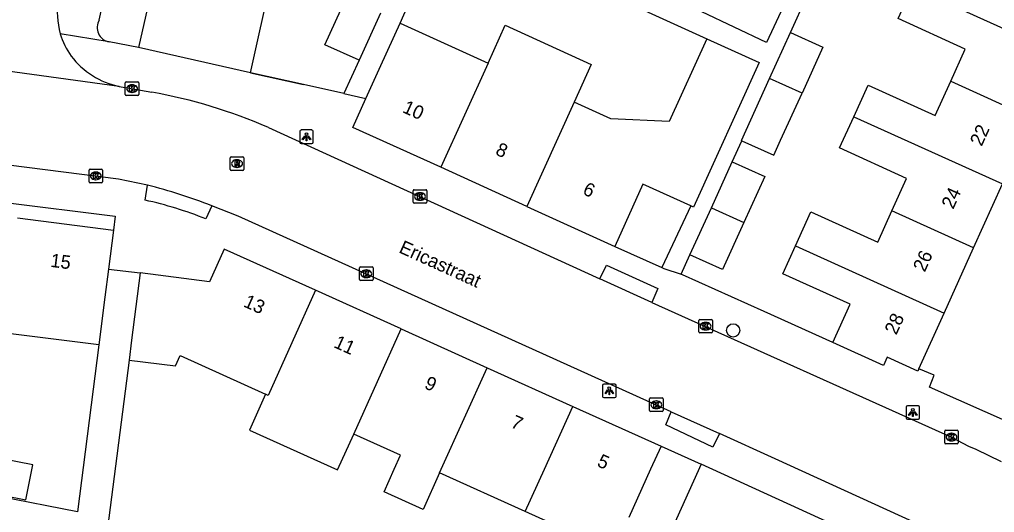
# Model space of a CAD drawing. Extents: x 161845 to 162341, y 381620 to 382158.
# Drawn here: x 162001.2 to 162073, y 381746.8 to 381783.1 of the extents above; entities that cross this region are included whole.
import ezdxf

# ---------------------------------------------------------------- set-up
doc = ezdxf.new("R2010")
doc.units = 0
for name, color, linetype in [('IMGEO_Boom', 7, 'Continuous'), ('IMGEO_Kolk', 7, 'Continuous'), ('IMGEO_Lichtpunt', 7, 'Continuous'), ('IMGEO_Muur', 7, 'Continuous'), ('IMGEO_Openbare_ruimte_label', 7, 'Continuous'), ('IMGEO_Pand', 7, 'Continuous'), ('IMGEO_Pand_nummerreeks', 7, 'Continuous'), ('IMGEO_Rijbaan_lokaal_open', 7, 'Continuous'), ('IMGEO_Rioolput', 7, 'Continuous'), ('IMGEO_Voetpad_open', 7, 'Continuous')]:
    doc.layers.add(name, color=color, linetype=linetype)

msp = doc.modelspace()

# ---------------------------------------------------------------- linework, layer by layer
at = {"layer": 'IMGEO_Boom'}
msp.add_circle((162053.769, 381760.227), 0.489, dxfattribs=at)
at = {"layer": 'IMGEO_Kolk'}
for p, q in [((162009.009, 381777.612), (162009.009, 381778.464)), ((162009.084, 381778.538), (162009.936, 381778.538)), ((162009.497, 381778.318), (162009.522, 381778.318)), ((162010.01, 381778.464), (162010.01, 381777.612)), ((162009.936, 381777.538), (162009.084, 381777.538)), ((162009.52, 381777.758), (162009.495, 381777.758)), ((162006.336, 381771.18), (162006.336, 381772.032)), ((162006.411, 381772.106), (162007.263, 381772.106)), ((162006.824, 381771.886), (162006.849, 381771.886)), ((162007.337, 381772.032), (162007.337, 381771.18)), ((162007.263, 381771.106), (162006.411, 381771.106)), ((162006.847, 381771.326), (162006.822, 381771.326)), ((162030.211, 381769.668), (162030.211, 381770.52)), ((162030.286, 381770.594), (162031.138, 381770.594)), ((162030.699, 381770.374), (162030.724, 381770.374)), ((162031.212, 381770.52), (162031.212, 381769.668)), ((162030.722, 381769.814), (162030.697, 381769.814)), ((162031.138, 381769.594), (162030.286, 381769.594)), ((162026.25, 381763.979), (162026.25, 381764.831)), ((162026.325, 381764.905), (162027.177, 381764.905)), ((162026.738, 381764.685), (162026.763, 381764.685)), ((162027.251, 381764.831), (162027.251, 381763.979)), ((162027.177, 381763.905), (162026.325, 381763.905)), ((162026.761, 381764.125), (162026.736, 381764.125)), ((162051.314, 381761.04), (162052.166, 381761.04)), ((162051.239, 381760.114), (162051.239, 381760.966)), ((162051.727, 381760.82), (162051.752, 381760.82)), ((162052.24, 381760.966), (162052.24, 381760.114)), ((162052.166, 381760.04), (162051.314, 381760.04)), ((162051.75, 381760.26), (162051.725, 381760.26)), ((162047.69, 381755.25), (162048.542, 381755.25)), ((162047.615, 381754.324), (162047.615, 381755.176)), ((162048.103, 381755.03), (162048.128, 381755.03)), ((162048.616, 381755.176), (162048.616, 381754.324)), ((162048.542, 381754.25), (162047.69, 381754.25)), ((162048.126, 381754.47), (162048.101, 381754.47)), ((162069.346, 381751.946), (162069.346, 381752.798)), ((162069.421, 381752.872), (162070.273, 381752.872)), ((162069.834, 381752.652), (162069.859, 381752.652)), ((162070.347, 381752.798), (162070.347, 381751.946)), ((162070.273, 381751.872), (162069.421, 381751.872)), ((162069.857, 381752.092), (162069.832, 381752.092))]:
    msp.add_line(p, q, dxfattribs=at)
for points in [[(162009.009, 381777.612), (162009.009, 381778.464)], [(162009.084, 381778.538), (162009.936, 381778.538)], [(162009.33, 381778.238), (162009.453, 381778.238), (162009.453, 381778.087), (162009.583, 381778.238), (162009.747, 381778.238), (162009.601, 381778.087), (162009.754, 381777.838), (162009.602, 381777.838), (162009.517, 381778.002), (162009.453, 381777.935), (162009.453, 381777.838), (162009.33, 381777.838), (162009.33, 381778.238)], [(162010.01, 381778.464), (162010.01, 381777.612)], [(162009.936, 381777.538), (162009.084, 381777.538)], [(162006.336, 381771.18), (162006.336, 381772.032)], [(162006.411, 381772.106), (162007.263, 381772.106)], [(162006.657, 381771.806), (162006.78, 381771.806), (162006.78, 381771.655), (162006.91, 381771.806), (162007.074, 381771.806), (162006.928, 381771.655), (162007.081, 381771.406), (162006.929, 381771.406), (162006.844, 381771.57), (162006.78, 381771.503), (162006.78, 381771.406), (162006.657, 381771.406), (162006.657, 381771.806)], [(162007.337, 381772.032), (162007.337, 381771.18)], [(162007.263, 381771.106), (162006.411, 381771.106)], [(162030.211, 381769.668), (162030.211, 381770.52)], [(162030.286, 381770.594), (162031.138, 381770.594)], [(162031.212, 381770.52), (162031.212, 381769.668)], [(162030.532, 381770.294), (162030.655, 381770.294), (162030.655, 381770.143), (162030.785, 381770.294), (162030.949, 381770.294), (162030.803, 381770.143), (162030.956, 381769.894), (162030.804, 381769.894), (162030.719, 381770.058), (162030.655, 381769.991), (162030.655, 381769.894), (162030.532, 381769.894), (162030.532, 381770.294)], [(162031.138, 381769.594), (162030.286, 381769.594)], [(162026.25, 381763.979), (162026.25, 381764.831)], [(162026.325, 381764.905), (162027.177, 381764.905)], [(162026.571, 381764.605), (162026.694, 381764.605), (162026.694, 381764.454), (162026.824, 381764.605), (162026.988, 381764.605), (162026.842, 381764.454), (162026.995, 381764.205), (162026.843, 381764.205), (162026.758, 381764.369), (162026.694, 381764.302), (162026.694, 381764.205), (162026.571, 381764.205), (162026.571, 381764.605)], [(162027.251, 381764.831), (162027.251, 381763.979)], [(162027.177, 381763.905), (162026.325, 381763.905)], [(162051.314, 381761.04), (162052.166, 381761.04)], [(162051.239, 381760.114), (162051.239, 381760.966)], [(162051.56, 381760.74), (162051.683, 381760.74), (162051.683, 381760.589), (162051.813, 381760.74), (162051.977, 381760.74), (162051.831, 381760.589), (162051.984, 381760.34), (162051.832, 381760.34), (162051.747, 381760.504), (162051.683, 381760.437), (162051.683, 381760.34), (162051.56, 381760.34), (162051.56, 381760.74)], [(162052.24, 381760.966), (162052.24, 381760.114)], [(162052.166, 381760.04), (162051.314, 381760.04)], [(162047.69, 381755.25), (162048.542, 381755.25)], [(162047.615, 381754.324), (162047.615, 381755.176)], [(162047.936, 381754.95), (162048.059, 381754.95), (162048.059, 381754.799), (162048.189, 381754.95), (162048.353, 381754.95), (162048.207, 381754.799), (162048.36, 381754.55), (162048.208, 381754.55), (162048.123, 381754.714), (162048.059, 381754.647), (162048.059, 381754.55), (162047.936, 381754.55), (162047.936, 381754.95)], [(162048.616, 381755.176), (162048.616, 381754.324)], [(162048.542, 381754.25), (162047.69, 381754.25)], [(162069.346, 381751.946), (162069.346, 381752.798)], [(162069.421, 381752.872), (162070.273, 381752.872)], [(162069.667, 381752.572), (162069.79, 381752.572), (162069.79, 381752.421), (162069.92, 381752.572), (162070.084, 381752.572), (162069.938, 381752.421), (162070.091, 381752.172), (162069.939, 381752.172), (162069.854, 381752.336), (162069.79, 381752.269), (162069.79, 381752.172), (162069.667, 381752.172), (162069.667, 381752.572)], [(162070.347, 381752.798), (162070.347, 381751.946)], [(162070.273, 381751.872), (162069.421, 381751.872)]]:
    msp.add_lwpolyline(points, dxfattribs=at)
for centre, start, end in [((162009.086, 381778.462), 91.55205, 178.44795), ((162009.086, 381778.462), 91.55205, 178.44795), ((162009.934, 381778.462), 1.55205, 88.44795), ((162009.934, 381778.462), 1.55205, 88.44795), ((162009.086, 381777.614), 181.55205, 268.44795), ((162009.086, 381777.614), 181.55205, 268.44795), ((162009.934, 381777.614), 271.55205, 358.44795), ((162009.934, 381777.614), 271.55205, 358.44795), ((162006.413, 381772.03), 91.55205, 178.44795), ((162006.413, 381772.03), 91.55205, 178.44795), ((162007.261, 381772.03), 1.55205, 88.44795), ((162007.261, 381772.03), 1.55205, 88.44795), ((162006.413, 381771.182), 181.55205, 268.44795), ((162006.413, 381771.182), 181.55205, 268.44795), ((162007.261, 381771.182), 271.55205, 358.44795), ((162007.261, 381771.182), 271.55205, 358.44795), ((162030.288, 381770.518), 91.55205, 178.44795), ((162030.288, 381770.518), 91.55205, 178.44795), ((162031.136, 381770.518), 1.55205, 88.44795), ((162031.136, 381770.518), 1.55205, 88.44795), ((162030.288, 381769.67), 181.55205, 268.44795), ((162030.288, 381769.67), 181.55205, 268.44795), ((162031.136, 381769.67), 271.55205, 358.44795), ((162031.136, 381769.67), 271.55205, 358.44795), ((162026.327, 381764.829), 91.55205, 178.44795), ((162026.327, 381764.829), 91.55205, 178.44795), ((162027.175, 381764.829), 1.55205, 88.44795), ((162027.175, 381764.829), 1.55205, 88.44795), ((162026.327, 381763.981), 181.55205, 268.44795), ((162026.327, 381763.981), 181.55205, 268.44795), ((162027.175, 381763.981), 271.55205, 358.44795), ((162027.175, 381763.981), 271.55205, 358.44795), ((162051.316, 381760.964), 91.55205, 178.44795), ((162051.316, 381760.964), 91.55205, 178.44795), ((162052.164, 381760.964), 1.55205, 88.44795), ((162052.164, 381760.964), 1.55205, 88.44795), ((162051.316, 381760.116), 181.55205, 268.44795), ((162051.316, 381760.116), 181.55205, 268.44795), ((162052.164, 381760.116), 271.55205, 358.44795), ((162052.164, 381760.116), 271.55205, 358.44795), ((162047.692, 381755.174), 91.55205, 178.44795), ((162047.692, 381755.174), 91.55205, 178.44795), ((162048.54, 381755.174), 1.55205, 88.44795), ((162048.54, 381755.174), 1.55205, 88.44795), ((162047.692, 381754.326), 181.55205, 268.44795), ((162047.692, 381754.326), 181.55205, 268.44795), ((162048.54, 381754.326), 271.55205, 358.44795), ((162048.54, 381754.326), 271.55205, 358.44795), ((162069.423, 381752.796), 91.55205, 178.44795), ((162069.423, 381752.796), 91.55205, 178.44795), ((162070.271, 381752.796), 1.55205, 88.44795), ((162070.271, 381752.796), 1.55205, 88.44795), ((162069.423, 381751.948), 181.55205, 268.44795), ((162069.423, 381751.948), 181.55205, 268.44795), ((162070.271, 381751.948), 271.55205, 358.44795), ((162070.271, 381751.948), 271.55205, 358.44795)]:
    msp.add_arc(centre, 0.0765, start, end, dxfattribs=at)
for centre, major_axis, ratio, start_param, end_param in [((162009.496, 381778.038), (-0.387, 0.002), 0.722429, 4.712389, 7.853982), ((162009.521, 381778.038), (-0.39, 0.002), 0.717154, 1.570796, 4.712389), ((162006.823, 381771.606), (-0.387, 0.002), 0.722429, 4.712389, 7.853982), ((162006.848, 381771.606), (-0.39, 0.002), 0.717154, 1.570796, 4.712389), ((162030.698, 381770.094), (-0.387, 0.002), 0.722429, 4.712389, 7.853982), ((162030.723, 381770.094), (-0.39, 0.002), 0.717154, 1.570796, 4.712389), ((162026.737, 381764.405), (-0.387, 0.002), 0.722429, 4.712389, 7.853982), ((162026.762, 381764.405), (-0.39, 0.002), 0.717154, 1.570796, 4.712389), ((162051.726, 381760.54), (-0.387, 0.002), 0.722429, 4.712389, 7.853982), ((162051.751, 381760.54), (-0.39, 0.002), 0.717154, 1.570796, 4.712389), ((162048.102, 381754.75), (-0.387, 0.002), 0.722429, 4.712389, 7.853982), ((162048.127, 381754.75), (-0.39, 0.002), 0.717154, 1.570796, 4.712389), ((162069.833, 381752.372), (-0.387, 0.002), 0.722429, 4.712389, 7.853982), ((162069.858, 381752.372), (-0.39, 0.002), 0.717154, 1.570796, 4.712389)]:
    msp.add_ellipse(centre, major_axis=major_axis, ratio=ratio, start_param=start_param, end_param=end_param, dxfattribs=at)
at = {"layer": 'IMGEO_Lichtpunt'}
for p, q in [((162021.854, 381774.896), (162021.854, 381774.089)), ((162021.854, 381774.896), (162021.854, 381774.089)), ((162022.756, 381774.991), (162021.948, 381774.991)), ((162022.756, 381774.991), (162021.948, 381774.991)), ((162022.85, 381774.089), (162022.85, 381774.896)), ((162022.85, 381774.089), (162022.85, 381774.896)), ((162021.948, 381773.995), (162022.756, 381773.995)), ((162021.948, 381773.995), (162022.756, 381773.995)), ((162044.152, 381756.178), (162044.152, 381755.371)), ((162044.152, 381756.178), (162044.152, 381755.371)), ((162045.054, 381756.273), (162044.246, 381756.273)), ((162045.054, 381756.273), (162044.246, 381756.273)), ((162045.148, 381755.371), (162045.148, 381756.178)), ((162045.148, 381755.371), (162045.148, 381756.178)), ((162044.246, 381755.277), (162045.054, 381755.277)), ((162044.246, 381755.277), (162045.054, 381755.277)), ((162066.505, 381754.584), (162066.505, 381753.777)), ((162066.505, 381754.584), (162066.505, 381753.777)), ((162067.407, 381754.679), (162066.599, 381754.679)), ((162067.407, 381754.679), (162066.599, 381754.679)), ((162067.501, 381753.777), (162067.501, 381754.584)), ((162067.501, 381753.777), (162067.501, 381754.584)), ((162066.599, 381753.683), (162067.407, 381753.683)), ((162066.599, 381753.683), (162067.407, 381753.683))]:
    msp.add_line(p, q, dxfattribs=at)
for points in [[(162022.228, 381774.56), (162022.267, 381774.532), (162022.079, 381774.27), (162022.041, 381774.297), (162022.228, 381774.56)], [(162022.33, 381774.512), (162022.377, 381774.512), (162022.377, 381774.19), (162022.33, 381774.19), (162022.33, 381774.512)], [(162022.44, 381774.532), (162022.478, 381774.559), (162022.665, 381774.297), (162022.626, 381774.269), (162022.44, 381774.532)], [(162044.526, 381755.842), (162044.565, 381755.814), (162044.377, 381755.552), (162044.339, 381755.579), (162044.526, 381755.842)], [(162044.628, 381755.794), (162044.675, 381755.794), (162044.675, 381755.472), (162044.628, 381755.472), (162044.628, 381755.794)], [(162044.738, 381755.814), (162044.776, 381755.841), (162044.963, 381755.579), (162044.924, 381755.551), (162044.738, 381755.814)], [(162066.879, 381754.248), (162066.918, 381754.22), (162066.73, 381753.958), (162066.692, 381753.985), (162066.879, 381754.248)], [(162066.981, 381754.2), (162067.028, 381754.2), (162067.028, 381753.878), (162066.981, 381753.878), (162066.981, 381754.2)], [(162067.091, 381754.22), (162067.129, 381754.247), (162067.316, 381753.985), (162067.277, 381753.957), (162067.091, 381754.22)]]:
    msp.add_lwpolyline(points, dxfattribs=at)
for centre in [(162022.353, 381774.694), (162044.651, 381755.976), (162067.004, 381754.382)]:
    msp.add_circle(centre, 0.0994, dxfattribs=at)
for centre, start, end in [((162021.948, 381774.896), 90, 180), ((162021.948, 381774.896), 90, 180), ((162022.756, 381774.896), 0, 90), ((162022.756, 381774.896), 0, 90), ((162021.948, 381774.089), 180, 270), ((162021.948, 381774.089), 180, 270), ((162022.756, 381774.089), 270, 0), ((162022.756, 381774.089), 270, 360), ((162044.246, 381756.178), 90, 180), ((162044.246, 381756.178), 90, 180), ((162045.054, 381756.178), 0, 90), ((162045.054, 381756.178), 0, 90), ((162044.246, 381755.371), 180, 270), ((162044.246, 381755.371), 180, 270), ((162045.054, 381755.371), 270, 0), ((162045.054, 381755.371), 270, 360), ((162066.599, 381754.584), 90, 180), ((162066.599, 381754.584), 90, 180), ((162067.407, 381754.584), 0, 90), ((162067.407, 381754.584), 0, 90), ((162066.599, 381753.777), 180, 270), ((162066.599, 381753.777), 180, 270), ((162067.407, 381753.777), 270, 0), ((162067.407, 381753.777), 270, 360)]:
    msp.add_arc(centre, 0.0946, start, end, dxfattribs=at)
at = {"layer": 'IMGEO_Muur'}
for points in [[(162018.222, 381779.214), (162022.125, 381778.338)], [(162061.101, 381759.332), (162056.054, 381761.616)], [(162061.772, 381745.637), (162051.408, 381750.366)]]:
    msp.add_lwpolyline(points, dxfattribs=at)
at = {"layer": 'IMGEO_Pand'}
for points in [[(162011.554, 381788.029), (162009.992, 381781.058)], [(162018.222, 381779.214), (162019.784, 381786.185)], [(162069.789, 381778.584), (162070.858, 381780.953), (162065.92, 381783.202), (162066.965, 381785.512)], [(162066.965, 381785.512), (162077.918, 381780.552)], [(162026.224, 381780.124), (162023.701, 381781.271), (162025.275, 381784.735)], [(162057.474, 381784.106), (162056.223, 381781.447), (162051.464, 381783.686)], [(162027.798, 381783.588), (162026.224, 381780.124)], [(162026.727, 381777.305), (162027.831, 381779.736), (162029.25, 381782.858)], [(162029.25, 381782.858), (162035.723, 381779.917)], [(162035.723, 381779.917), (162036.99, 381782.704), (162043.326, 381779.825), (162042.06, 381777.038)], [(162056.45, 381778.782), (162057.991, 381782.173)], [(162057.991, 381782.173), (162060.383, 381781.087), (162058.843, 381777.698)], [(162051.841, 381781.715), (162049.069, 381775.611), (162044.758, 381775.812), (162042.06, 381777.038)], [(162051.841, 381781.715), (162055.694, 381779.965), (162050.853, 381769.311), (162050.655, 381769.401)], [(162018.222, 381779.214), (162009.992, 381781.058)], [(162035.723, 381779.917), (162032.236, 381772.242)], [(162054.405, 381774.198), (162054.374, 381774.212), (162056.45, 381778.782)], [(162058.843, 381777.698), (162056.45, 381778.782)], [(162062.654, 381775.972), (162063.703, 381778.29), (162068.645, 381776.051), (162069.789, 381778.584)], [(162069.789, 381778.584), (162075.797, 381775.863)], [(162054.405, 381774.198), (162056.766, 381773.126), (162057.268, 381774.231), (162058.843, 381777.698)], [(162032.236, 381772.242), (162025.763, 381775.183), (162026.727, 381777.305)], [(162042.06, 381777.038), (162038.572, 381769.363)], [(162065.465, 381769.039), (162066.546, 381771.429), (162061.613, 381773.671), (162062.654, 381775.972)], [(162062.654, 381775.972), (162073.603, 381771.013)], [(162052.164, 381769.266), (162053.705, 381772.657)], [(162053.705, 381772.657), (162056.097, 381771.571), (162054.557, 381768.182)], [(162038.572, 381769.363), (162032.236, 381772.242)], [(162050.655, 381769.401), (162047.129, 381771.003), (162045.047, 381766.421)], [(162071.478, 381766.316), (162073.603, 381771.013)], [(162038.572, 381769.363), (162045.047, 381766.421)], [(162050.59, 381765.801), (162052.164, 381769.266)], [(162052.164, 381769.266), (162054.557, 381768.182)], [(162058.368, 381766.456), (162059.499, 381768.952), (162064.418, 381766.726), (162065.465, 381769.039)], [(162071.478, 381766.316), (162065.465, 381769.039)], [(162001.068, 381768.526), (162008.135, 381767.624)], [(162054.557, 381768.182), (162052.982, 381764.715), (162050.59, 381765.801)], [(162008.135, 381767.624), (162007.766, 381764.735)], [(162023.027, 381763.18), (162016.3, 381766.217), (162015.212, 381763.807), (162010.108, 381764.458)], [(162061.101, 381759.332), (162062.381, 381762.156), (162057.435, 381764.397), (162058.368, 381766.456)], [(162058.368, 381766.456), (162069.301, 381761.504)], [(162069.301, 381761.504), (162071.478, 381766.316)], [(162007.766, 381764.735), (162007.502, 381762.665), (162007.054, 381759.154)], [(162010.108, 381764.458), (162009.475, 381759.499), (162009.289, 381758.044)], [(162023.027, 381763.18), (162019.526, 381755.438), (162019.345, 381755.52)], [(162029.328, 381760.335), (162023.027, 381763.18)], [(162067.446, 381757.401), (162069.301, 381761.504)], [(162025.827, 381752.593), (162029.328, 381760.335)], [(162029.328, 381760.335), (162035.655, 381757.478)], [(162007.054, 381759.154), (162000.001, 381760.054)], [(162067.446, 381757.401), (162067.371, 381757.236), (162065.115, 381758.257), (162064.835, 381757.639), (162061.101, 381759.332)], [(162009.289, 381758.044), (162012.694, 381757.609), (162013.037, 381758.368), (162019.345, 381755.52)], [(162032.154, 381749.736), (162032.273, 381750), (162035.655, 381757.478)], [(162035.655, 381757.478), (162041.966, 381754.629)], [(162019.345, 381755.52), (162018.151, 381752.877), (162024.634, 381749.95), (162025.827, 381752.593)], [(162038.465, 381746.887), (162039.873, 381750), (162041.966, 381754.629)], [(162041.966, 381754.629), (162048.46, 381751.697)], [(162032.154, 381749.736), (162030.939, 381747.046), (162028.06, 381748.346), (162028.807, 381750), (162029.275, 381751.036), (162025.827, 381752.593)], [(162048.46, 381751.697), (162047.692, 381750), (162046.08, 381746.435)], [(162048.46, 381751.697), (162051.408, 381750.366)], [(161998.285, 381748.408), (162001.694, 381747.739), (162002.202, 381750.327), (161998.795, 381750.995)], [(162051.408, 381750.366), (162049.031, 381745.101)], [(162038.465, 381746.887), (162032.154, 381749.736)], [(162044.624, 381743.216), (162044.525, 381743.261), (162044.858, 381744), (162038.465, 381746.887)]]:
    msp.add_lwpolyline(points, dxfattribs=at)
at = {"layer": 'IMGEO_Rijbaan_lokaal_open'}
for points in [[(162008.56, 381778.199), (161991.196, 381780.587)], [(162008.56, 381778.199), (162009.14, 381778.097), (162010.959, 381777.779)], [(162010.639, 381770.93), (162008.503, 381771.36), (161974.338, 381775.707)], [(162019.542, 381775.175), (162043.964, 381764.024)], [(162049.197, 381754.238), (162017.318, 381768.637), (162015.372, 381769.412)], [(162047.793, 381762.29), (162043.964, 381764.024)], [(162047.793, 381762.29), (162069.847, 381752.372), (162071.089, 381751.71), (162071.642, 381751.481), (162073.51, 381750.574)], [(162049.197, 381754.238), (162052.77, 381752.631)], [(162068.985, 381745.23), (162068.214, 381745.584), (162056.86, 381750.762), (162052.77, 381752.631)]]:
    msp.add_lwpolyline(points, dxfattribs=at)
for centre, radius, start, end in [((162009.557, 381783.641), 5.558, 169.9636, 196.25021), ((162009.535, 381783.649), 5.539, 196.38998, 215.45514), ((162009.77, 381784.027), 5.952, 217.10523, 258.2716), ((162004.162, 381739.93), 38.455, 66.42555, 79.81986), ((162001.206, 381733.382), 38.714, 68.53697, 75.89815)]:
    msp.add_arc(centre, radius, start, end, dxfattribs=at)
at = {"layer": 'IMGEO_Rioolput'}
for p, q in [((162016.739, 381772.089), (162016.739, 381772.941)), ((162016.814, 381773.015), (162017.666, 381773.015)), ((162017.227, 381772.795), (162017.252, 381772.795)), ((162017.74, 381772.941), (162017.74, 381772.089)), ((162017.666, 381772.015), (162016.814, 381772.015)), ((162017.25, 381772.235), (162017.225, 381772.235))]:
    msp.add_line(p, q, dxfattribs=at)
for points in [[(162016.739, 381772.089), (162016.739, 381772.941)], [(162016.814, 381773.015), (162017.666, 381773.015)], [(162017.328, 381772.713), (162017.076, 381772.715), (162017.076, 381772.315)], [(162017.254, 381772.634), (162017.2, 381772.634), (162017.2, 381772.553)], [(162017.2, 381772.553), (162017.252, 381772.553)], [(162017.74, 381772.941), (162017.74, 381772.089)], [(162017.666, 381772.015), (162016.814, 381772.015)], [(162017.076, 381772.315), (162017.2, 381772.315), (162017.2, 381772.477), (162017.211, 381772.477)], [(162017.258, 381772.448), (162017.329, 381772.315), (162017.469, 381772.315), (162017.404, 381772.441)]]:
    msp.add_lwpolyline(points, dxfattribs=at)
for centre, radius, start, end in [((162016.816, 381772.939), 0.0765, 91.55205, 178.44795), ((162016.816, 381772.939), 0.0765, 91.55205, 178.44795), ((162017.236, 381772.742), 0.19, 274.7715, 282.96867), ((162017.26, 381772.538), 0.0964, 77.00612, 93.18647), ((162017.274, 381772.595), 0.0378, 276.66336, 79.67722), ((162017.327, 381772.603), 0.109, 350.36119, 89.41601), ((162017.325, 381772.603), 0.112, 277.58423, 350.98172), ((162017.309, 381772.388), 0.108, 29.51342, 73.79051), ((162017.664, 381772.939), 0.0765, 1.55205, 88.44795), ((162017.664, 381772.939), 0.0765, 1.55205, 88.44795), ((162016.816, 381772.091), 0.0765, 181.55205, 268.44795), ((162016.816, 381772.091), 0.0765, 181.55205, 268.44795), ((162017.21, 381772.424), 0.0533, 26.02933, 88.69889), ((162017.664, 381772.091), 0.0765, 271.55205, 358.44795), ((162017.664, 381772.091), 0.0765, 271.55205, 358.44795)]:
    msp.add_arc(centre, radius, start, end, dxfattribs=at)
for centre, major_axis, ratio, start_param, end_param in [((162017.226, 381772.515), (-0.387, 0.002), 0.722429, 4.712389, 7.853982), ((162017.251, 381772.515), (-0.39, 0.002), 0.717154, 1.570796, 4.712389)]:
    msp.add_ellipse(centre, major_axis=major_axis, ratio=ratio, start_param=start_param, end_param=end_param, dxfattribs=at)
at = {"layer": 'IMGEO_Voetpad_open'}
for points in [[(162007.085, 381783.093), (162014.199, 381815.078)], [(162032.227, 381790.054), (162032.446, 381790.557), (162051.841, 381781.715)], [(162029.25, 381782.858), (162031.254, 381787.46)], [(162057.991, 381782.173), (162059.206, 381784.848)], [(162007.821, 381781.474), (162004.221, 381782.086)], [(162009.992, 381781.058), (162007.821, 381781.474)], [(162026.224, 381780.124), (162025.108, 381777.668)], [(162025.108, 381777.668), (162022.125, 381778.338), (162018.222, 381779.214)], [(162025.108, 381777.668), (162026.727, 381777.305)], [(162053.705, 381772.657), (162054.405, 381774.198)], [(161974.073, 381772.99), (162000, 381769.681), (162008.257, 381768.648), (162008.135, 381767.624)], [(162010.464, 381769.821), (162010.639, 381770.93)], [(162015.372, 381769.412), (162014.939, 381768.441)], [(162050.655, 381769.401), (162048.513, 381764.865)], [(162045.047, 381766.421), (162048.513, 381764.865)], [(162049.942, 381764.37), (162050.59, 381765.801)], [(162007.766, 381764.735), (162010.108, 381764.458)], [(162043.964, 381764.024), (162044.441, 381765.033), (162048.229, 381763.319), (162047.793, 381762.29)], [(162048.513, 381764.865), (162048.674, 381764.793), (162049.942, 381764.37)], [(162061.101, 381759.332), (162056.054, 381761.616), (162050.052, 381764.333), (162049.942, 381764.37)], [(162007.054, 381759.154), (162005.486, 381746.869), (161988.151, 381750.259)], [(162009.289, 381758.044), (162007.608, 381744.889), (162008.191, 381744.624)], [(162074.49, 381753.282), (162068.219, 381756.057), (162068.579, 381756.936), (162067.446, 381757.401)], [(162052.77, 381752.631), (162052.283, 381751.622), (162048.804, 381753.263), (162049.197, 381754.238)], [(162061.772, 381745.637), (162051.408, 381750.366)]]:
    msp.add_lwpolyline(points, dxfattribs=at)
for centre, radius, start, end in [((162008.018, 381782.54), 1.084, 149.35003, 259.54321), ((162004.516, 381742.589), 27.874, 68.04262, 77.67996)]:
    msp.add_arc(centre, radius, start, end, dxfattribs=at)

# ---------------------------------------------------------------- texts
at = {"layer": 'IMGEO_Openbare_ruimte_label'}
msp.add_text('Ericastraat', height=1, rotation=335.61293, dxfattribs=at).set_placement((162029.09, 381765.992))
at = {"layer": 'IMGEO_Pand_nummerreeks'}
for s, rotation, p in [('10', 335.56455, (162029.353, 381776.32)), ('22', 65.66101, (162072.07, 381773.737)), ('8', 335.56455, (162036.201, 381773.209)), ('6', 335.56335, (162042.626, 381770.29)), ('24', 65.66101, (162069.975, 381769.106)), ('26', 65.66101, (162067.879, 381764.473)), ('15', 352.72853, (162003.457, 381764.914)), ('13', 335.70086, (162017.644, 381762.011)), ('28', 65.66101, (162065.784, 381759.841)), ('11', 335.70086, (162024.291, 381759.01)), ('9', 335.70118, (162030.963, 381755.998)), ('7', 335.70118, (162037.321, 381753.127)), ('5', 335.70118, (162043.68, 381750.256))]:
    msp.add_text(s, height=1, rotation=rotation, dxfattribs=at).set_placement(p)

doc.saveas('drawing.dxf')
